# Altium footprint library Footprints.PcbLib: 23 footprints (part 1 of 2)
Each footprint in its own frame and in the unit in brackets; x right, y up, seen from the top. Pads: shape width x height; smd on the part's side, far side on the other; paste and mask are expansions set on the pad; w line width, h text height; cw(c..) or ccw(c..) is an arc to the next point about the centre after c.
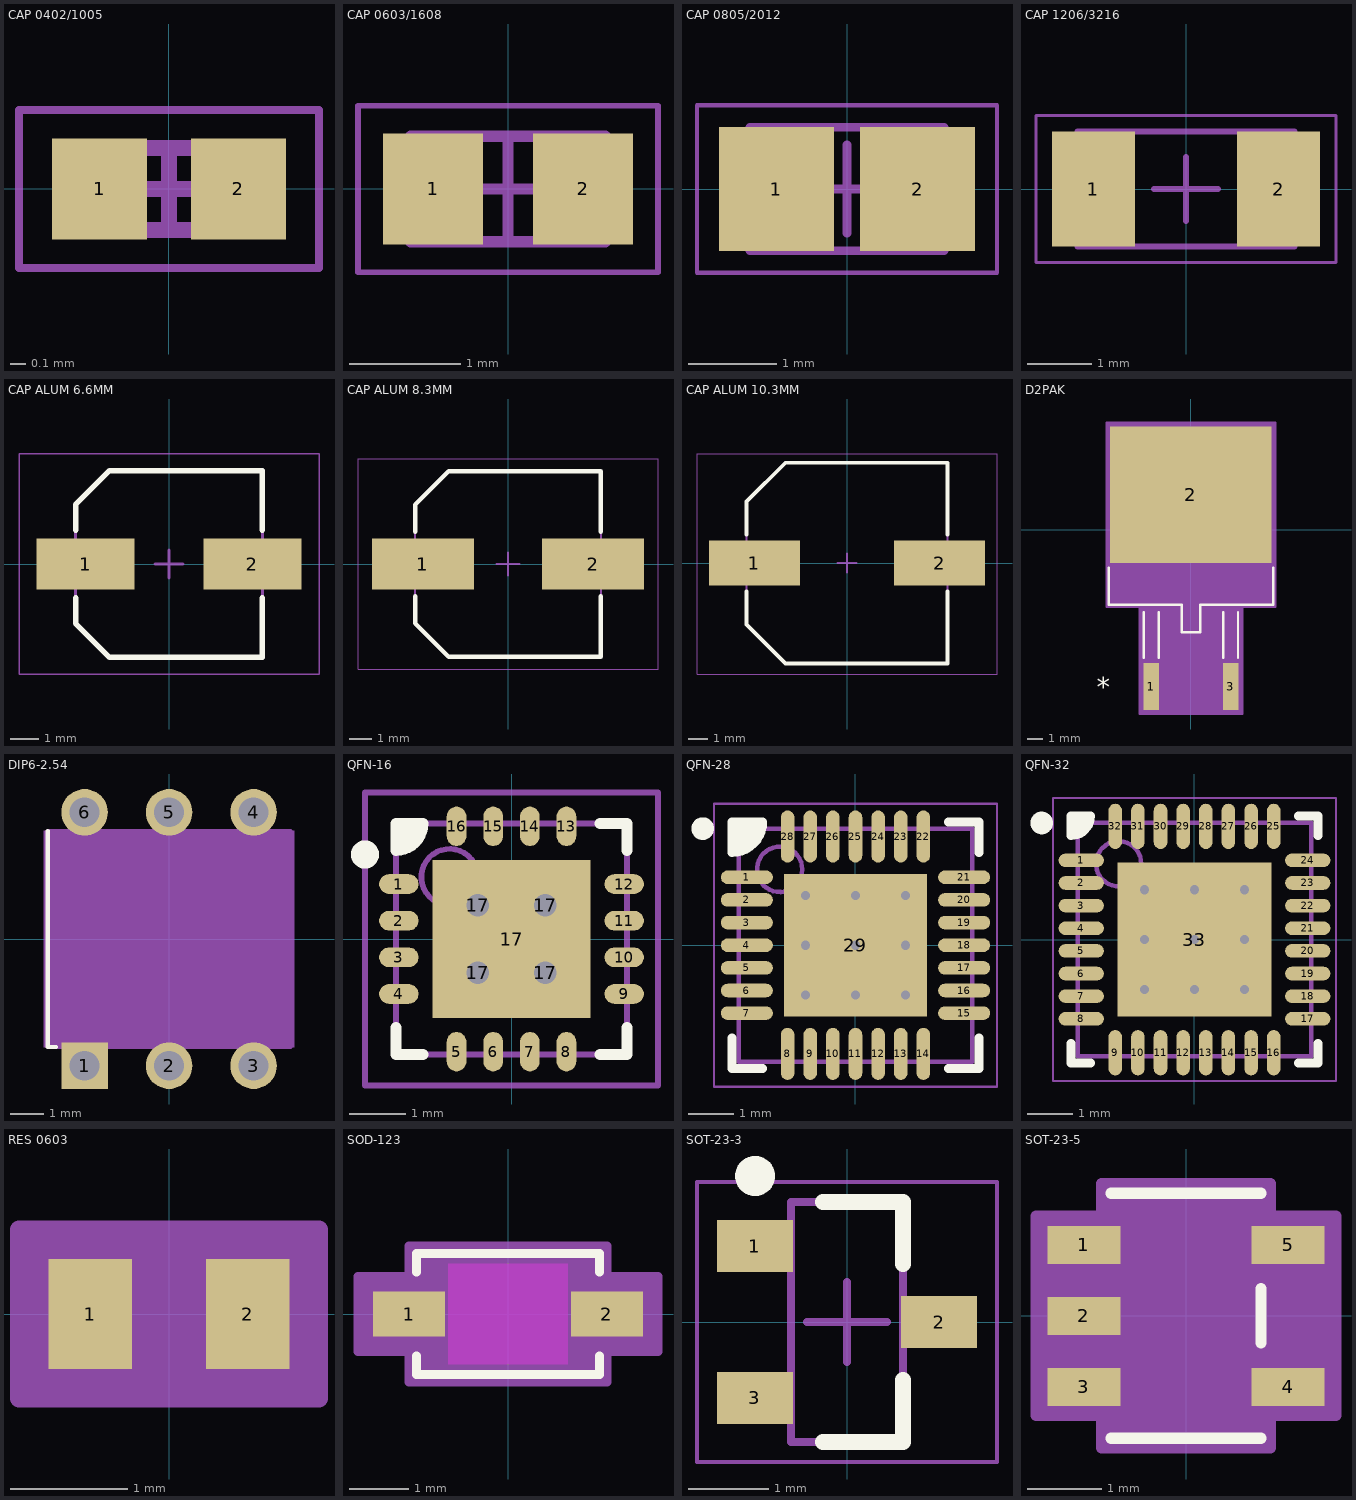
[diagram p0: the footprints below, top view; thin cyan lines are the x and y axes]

## CAP 0402/1005 [mm] "Chip Capacitor, 2-Leads, Body 1.02x0.51mm, IPC Medium Density"
height 0.52
pads (2):
  rect 0.6x0.64 smd: 1(-0.44,0) 2(0.44,0)
Mechanical 13:
  lines w0.1: -0.515,-0.26 0.515,-0.26 0.515,0.26 -0.515,0.26 -0.515,-0.26
Mechanical 15:
  lines w0.05: -0.95,-0.5 0.95,-0.5 0.95,0.5 -0.95,0.5 -0.95,-0.5
  lines w0.1: -0.26,0 0.26,0 ; 0,-0.26 0,0.26
3D body "0402 cap.STEP": height 0.52, standoff 0, extent -0.5,-0.262 0.5,0.262

## CAP 0603/1608 [mm] "Chip Capacitor, 2-Leads, Body 1.60x0.80mm, IPC Medium Density"
height 0.89
pads (2):
  rect 0.9x1 smd: 1(-0.675,0) 2(0.675,0)
Mechanical 13:
  lines w0.1: -0.875,-0.475 -0.875,0.475 0.875,0.475 0.875,-0.475 -0.875,-0.475
Mechanical 15:
  lines w0.05: -1.35,-0.75 -1.35,0.75 1.35,0.75 1.35,-0.75 -1.35,-0.75
  lines w0.1: -0.475,0 0.475,0 ; 0,-0.475 0,0.475
3D body "0603 cap.STEP": height 0.82, standoff 0, extent -0.8,-0.412 0.8,0.412

## CAP 0805/2012 [mm] "Chip Capacitor, 2-Leads, Body 2.00x1.20mm, IPC Medium Density"
height 1.15
pads (2):
  rect 1.3x1.4 smd: 1(-0.8,0) 2(0.8,0)
Mechanical 13:
  lines w0.1: -1.1,-0.7 1.1,-0.7 1.1,0.7 -1.1,0.7 -1.1,-0.7
Mechanical 15:
  lines w0.05: -1.7,-0.95 1.7,-0.95 1.7,0.95 -1.7,0.95 -1.7,-0.95
  lines w0.1: -0.5,0 0.5,0 ; 0,-0.5 0,0.5
3D body "0805 cap.STEP": height 1.26, standoff -0.02, extent -1,-0.637 1,0.637

## CAP 1206/3216 [mm] "Chip Capacitor, 2-Leads, Body 3.25x1.60mm, IPC Medium Density"
height 1.6
pads (2):
  rect 1.3x1.8 smd: 1(-1.45,0) 2(1.45,0)
Mechanical 13:
  lines w0.1: -1.7,-0.9 1.7,-0.9 1.7,0.9 -1.7,0.9 -1.7,-0.9
Mechanical 15:
  lines w0.05: -2.35,-1.15 2.35,-1.15 2.35,1.15 -2.35,1.15 -2.35,-1.15
  lines w0.1: -0.5,0 0.5,0 ; 0,-0.5 0,0.5
3D body "1206 cap.STEP": height 1.62, standoff 0, extent -1.6,-0.812 1.6,0.812

## CAP ALUM 6.6MM [mm] "Aluminum Electrolytic Capacitor, Body 6.60x6.60x7.70mm, IPC Low Density"
height 7.7
pads (2):
  rect 3.45x1.8 smd: 1(-2.95,0) 2(2.95,0)
Top Overlay:
  lines w0.2: -3.3,-1.2 -3.3,-2.1 -2.1,-3.3 3.3,-3.3 3.3,-1.2 ; -3.3,1.2 -3.3,2.1 -2.1,3.3 3.3,3.3 3.3,1.2
Mechanical 13:
  lines w0.1: -3.3,-2.1 -2.1,-3.3 3.3,-3.3 3.3,3.3 -2.1,3.3 -3.3,2.1 -3.3,-2.1
Mechanical 15:
  lines w0.05: -5.3,-3.9 -5.3,3.9 5.3,3.9 5.3,-3.9 -5.3,-3.9
  lines w0.1: -0.5,0 0.5,0 ; 0,-0.5 0,0.5
3D body "CAP ALUM 6_6mm.STEP": height 7.7, standoff 0, extent -3.5,-3.3 3.5,3.3

## CAP ALUM 8.3MM [mm] "Aluminum Electrolytic Capacitor, Body 8.30x8.30x10.50mm, IPC Low Density"
height 10.5
pads (2):
  rect 4.55x2.3 smd: 1(-3.8,0) 2(3.8,0)
Top Overlay:
  lines w0.2: -4.15,-1.45 -4.15,-2.65 -2.65,-4.15 4.15,-4.15 4.15,-1.45 ; -4.15,1.45 -4.15,2.65 -2.65,4.15 4.15,4.15 4.15,1.45
Mechanical 13:
  lines w0.1: -4.15,-2.65 -4.15,2.65 -2.65,4.15 4.15,4.15 4.15,-4.15 -2.65,-4.15 -4.15,-2.65
Mechanical 15:
  lines w0.05: -6.7,-4.7 6.7,-4.7 6.7,4.7 -6.7,4.7 -6.7,-4.7
  lines w0.1: -0.5,0 0.5,0 ; 0,-0.5 0,0.5
3D body "CAP ALUM 8_3mm.STEP": height 10.5, standoff 0, extent -4.95,-4.15 4.95,4.15

## CAP ALUM 10.3MM [mm] "Aluminum Electrolytic Capacitor, Body 10.30x10.30x10.50mm, IPC Low Density"
height 10.5
pads (2):
  rect 4.65x2.3 smd: 1(-4.75,0) 2(4.75,0)
Top Overlay:
  lines w0.2: -5.15,-1.45 -5.15,-3.15 -3.15,-5.15 5.15,-5.15 5.15,-1.45 ; -5.15,1.45 -5.15,3.15 -3.15,5.15 5.15,5.15 5.15,1.45
Mechanical 13:
  lines w0.1: -5.15,-3.15 -3.15,-5.15 5.15,-5.15 5.15,5.15 -3.15,5.15 -5.15,3.15 -5.15,-3.15
Mechanical 15:
  lines w0.05: -7.7,-5.7 -7.7,5.6 7.7,5.6 7.7,-5.7 -7.7,-5.7
  lines w0.1: -0.5,0 0.5,0 ; 0,-0.5 0,0.5
3D body "CAP ALUM 10_3mm.STEP": height 10.5, standoff 0, extent -5.8,-5.15 5.8,5.15

## D2PAK [mil]
pads (3):
  rect 39x118 smd paste+0 mask+0: 1(-100,-395) 3(100,-395)
  rect 407x343 smd paste+0 mask+0: 2(0,88.5)
Top Overlay:
  lines w6: -207.5,-95.47 -207.5,-189 -23.5,-189 -23.5,-258 23.5,-258 23.5,-189 207.5,-189 207.5,-95.47 ; -118.5,-322 -118.5,-208 ; -81.5,-322 -81.5,-208 ; 81.5,-322 81.5,-208 ; 118.5,-322 118.5,-208
  text "*" at -237.5,-420 h50
Mechanical 13:
  lines w1: -202.5,-184 202.5,-184 202.5,184 -202.5,184 -202.5,-184 ; -118.5,-440 -118.5,-184 -81.5,-184 -81.5,-440 -118.5,-440 ; -18.5,-253 -18.5,-184 18.5,-184 18.5,-253 -18.5,-253 ; 81.5,-440 81.5,-184 118.5,-184 118.5,-440 81.5,-440
  text "*" at -112.5,-199 h50
Mechanical 15:
  region: -212.5,-194 -212.5,194 -212.5,270 212.5,270 212.5,194 212.5,-194 129.5,-194 129.5,-464 -129.5,-464 -129.5,-194
  lines w6: -212.5,-194 -212.5,194 -212.5,270 212.5,270 212.5,194 212.5,-194 129.5,-194 129.5,-464 -129.5,-464 -129.5,-194 -212.5,-194
3D body "D2PAK_T2550_STM.step": height 181.1, standoff -2.01, extent -202.48,-440 202.48,239.02

## DIP6-2.54 [mm]
pads (6):
  rect 1.4x1.4 hole 0.9: 1(-2.54,-3.81)
  round 1.4 hole 0.9: 2(0,-3.81) 3(2.54,-3.81) 4(2.54,3.81) 5(0,3.81) 6(-2.54,3.81)
Top Overlay:
  lines w0.127: -3.65,3.25 -3.65,-3.25 -3.4,-3.25
Mechanical 13:
  lines w0.127: -3.65,-3.25 3.65,-3.25 ; -3.65,3.25 3.65,3.25
Mechanical 15:
  region: 3.76,-3.255 -3.766,-3.255 -3.766,3.25 3.76,3.25
3D body "4N35.STEP": height 3.81, standoff -3.94, extent -3.56,-4.405 3.56,4.405

## QFN-16 [mm] "QFN, 16-Leads, Body 4.1x4.1mm (max), Pitch 0.65mm, IPC Medium Density"
height 1
pads (21):
  oval 0.7x0.35 smd: 1(-2,0.975) 2(-2,0.325) 3(-2,-0.325) 4(-2,-0.975) 9(2,-0.975) 10(2,-0.325) 11(2,0.325) 12(2,0.975)
  oval 0.35x0.7 smd: 5(-0.975,-2) 6(-0.325,-2) 7(0.325,-2) 8(0.975,-2) 13(0.975,2) 14(0.325,2) 15(-0.325,2) 16(-0.975,2)
  round 0.8 hole 0.4 unplated: 17(-0.6,-0.6) 17(-0.6,0.6) 17(0.6,-0.6) 17(0.6,0.6)
  rect 2.8x2.8 smd: 17(0,0)
Top Overlay:
  circle w0.25: c-2.6,1.5 r0.125
  region: -2.05,2.05 -1.575,2.05 -1.575,1.925 -1.9,1.6 -2.05,1.6
  lines w0.2: -2.05,-1.575 -2.05,-2.05 -1.575,-2.05 ; 1.575,-2.05 2.05,-2.05 2.05,-1.575 ; 1.575,2.05 2.05,2.05 2.05,1.575 ; -2.05,1.575 ccw(c-2.05,2.05) -1.575,2.05 -2.05,2.05 -2.05,1.575
Mechanical 13:
  circle w0.1: c-1.1,1.1 r0.5
  lines w0.1: -2.05,-2.05 -2.05,2.05 2.05,2.05 2.05,-2.05 -2.05,-2.05
Mechanical 15:
  lines w0.1: -0.5,0 0.5,0 ; 0,-0.5 0,0.5 ; -2.6,-2.6 -2.6,2.6 2.6,2.6 2.6,-2.6 -2.6,-2.6
3D body: height 1, standoff 0.08, extent -2.05,-2.05 2.05,2.05

## QFN-28 [mm] "QFN, 28-Leads, Body 5.00x5.00mm, Pitch 0.50mm, Thermal Pad 3.15x3.15mm, IPC Medium Density"
height 1
pads (29):
  oval 1.15x0.3 smd: 1(-2.4,1.5) 2(-2.4,1) 3(-2.4,0.5) 4(-2.4,0) 5(-2.4,-0.5) 6(-2.4,-1) 7(-2.4,-1.5) 15(2.4,-1.5) 16(2.4,-1) 17(2.4,-0.5) 18(2.4,0) 19(2.4,0.5) 20(2.4,1) 21(2.4,1.5)
  oval 0.3x1.15 smd: 8(-1.5,-2.4) 9(-1,-2.4) 10(-0.5,-2.4) 11(0,-2.4) 12(0.5,-2.4) 13(1,-2.4) 14(1.5,-2.4) 22(1.5,2.4) 23(1,2.4) 24(0.5,2.4) 25(0,2.4) 26(-0.5,2.4) 27(-1,2.4) 28(-1.5,2.4)
  rect 3.15x3.15 smd: 29(0,0)
via 1.1,-1.1 diameter 0.5 hole 0.2
via 0,-1.1 diameter 0.5 hole 0.2
via -1.1,-1.1 diameter 0.5 hole 0.2
via 1.1,0 diameter 0.5 hole 0.2
via 0,0 diameter 0.5 hole 0.2
via -1.1,0 diameter 0.5 hole 0.2
via 1.1,1.1 diameter 0.5 hole 0.2
via 0,1.1 diameter 0.5 hole 0.2
via -1.1,1.1 diameter 0.5 hole 0.2
Top Overlay:
  circle w0.25: c-3.375,2.575 r0.125
  region: -2.725,2.725 -2.05,2.725 -2.05,2.659 -2.076,2.528 -2.127,2.405 -2.201,2.295 -2.295,2.201 -2.405,2.127 -2.528,2.076 -2.659,2.05 -2.725,2.05
  lines w0.2: -2.725,-2.05 -2.725,-2.725 -2.05,-2.725 ; 2.05,-2.725 2.725,-2.725 2.725,-2.05 ; 2.05,2.725 2.725,2.725 2.725,2.05 ; -2.725,2.05 ccw(c-2.725,2.725) -2.05,2.725 -2.725,2.725 -2.725,2.05
Mechanical 13:
  circle w0.1: c-1.675,1.675 r0.5
  lines w0.1: -2.575,-2.575 2.575,-2.575 2.575,2.575 -2.575,2.575 -2.575,-2.575
Mechanical 15:
  lines w0.05: -3.125,-3.125 3.125,-3.125 3.125,3.125 -3.125,3.125 -3.125,-3.125
  lines w0.1: -0.5,0 0.5,0 ; 0,-0.5 0,0.5
3D body: height 1, standoff 0.01, extent -2.575,-2.575 2.575,2.575

## QFN-32 [mm] "QFN, 32-Leads, Body 5.00x5.00mm, Pitch 0.50mm, Thermal Pad 3.40x3.40mm, IPC Medium Density"
height 1
pads (33):
  oval 1x0.3 smd: 1(-2.5,1.75) 2(-2.5,1.25) 3(-2.5,0.75) 4(-2.5,0.25) 5(-2.5,-0.25) 6(-2.5,-0.75) 7(-2.5,-1.25) 8(-2.5,-1.75) 17(2.5,-1.75) 18(2.5,-1.25) 19(2.5,-0.75) 20(2.5,-0.25) 21(2.5,0.25) 22(2.5,0.75) 23(2.5,1.25) 24(2.5,1.75)
  oval 0.3x1 smd: 9(-1.75,-2.5) 10(-1.25,-2.5) 11(-0.75,-2.5) 12(-0.25,-2.5) 13(0.25,-2.5) 14(0.75,-2.5) 15(1.25,-2.5) 16(1.75,-2.5) 25(1.75,2.5) 26(1.25,2.5) 27(0.75,2.5) 28(0.25,2.5) 29(-0.25,2.5) 30(-0.75,2.5) 31(-1.25,2.5) 32(-1.75,2.5)
  rect 3.4x3.4 smd: 33(0,0)
via 1.1,-1.1 diameter 0.5 hole 0.2
via 0,-1.1 diameter 0.5 hole 0.2
via -1.1,-1.1 diameter 0.5 hole 0.2
via 1.1,0 diameter 0.5 hole 0.2
via 0,0 diameter 0.5 hole 0.2
via -1.1,0 diameter 0.5 hole 0.2
via 1.1,1.1 diameter 0.5 hole 0.2
via 0,1.1 diameter 0.5 hole 0.2
via -1.1,1.1 diameter 0.5 hole 0.2
Top Overlay:
  circle w0.25: c-3.375,2.575 r0.125
  region: -2.725,2.725 -2.3,2.725 -2.3,2.64 -2.365,2.484 -2.484,2.365 -2.64,2.3 -2.725,2.3
  lines w0.2: -2.725,-2.3 -2.725,-2.725 -2.3,-2.725 ; 2.3,-2.725 2.725,-2.725 2.725,-2.3 ; 2.3,2.725 2.725,2.725 2.725,2.3 ; -2.725,2.3 ccw(c-2.725,2.725) -2.3,2.725 -2.725,2.725 -2.725,2.3
Mechanical 13:
  circle w0.1: c-1.675,1.675 r0.5
  lines w0.1: -2.575,-2.575 2.575,-2.575 2.575,2.575 -2.575,2.575 -2.575,-2.575
Mechanical 15:
  lines w0.05: -3.125,-3.125 3.125,-3.125 3.125,3.125 -3.125,3.125 -3.125,-3.125
  lines w0.1: -0.5,0 0.5,0 ; 0,-0.5 0,0.5
3D body: height 1, standoff 0.01, extent -2.575,-2.575 2.575,2.575

## RES 0603 [mil]
pads (2):
  rect 28x37 smd paste-18.5 mask-18.5: 1(-26.5,0) 2(26.5,0)
Mechanical 13:
  lines w1: -32.5,-18.5 -32.5,18.5 ; -32.5,-18.5 -12.5,-18.5 -12.5,18.5 -32.5,18.5 ; -32.5,-18.5 32.5,-18.5 ; -32.5,-18.5 -32.5,18.5 ; -32.5,18.5 32.5,18.5 ; 32.5,-18.5 12.5,-18.5 12.5,18.5 32.5,18.5 ; 32.5,-18.5 32.5,18.5 ; 32.5,-18.5 32.5,18.5
Mechanical 15:
  region: 50.5,-28.5 -50.5,-28.5 -50.5,28.5 50.5,28.5
  lines w6: -50.5,-28.5 -50.5,28.5 50.5,28.5 50.5,-28.5 -50.5,-28.5
3D body "RES_CRCW_0603.step": height 20, standoff 0, extent -32.52,-18.5 32.52,18.5

## SOD-123 [mil]
pads (2):
  rect 48x30 smd paste+0 mask+0: 1(-66,0) 2(66,0)
Top Overlay:
  lines w6: -61,-28.1 -61,-40.5 61,-40.5 61,-28.1 ; -61,28.1 -61,40.5 61,40.5 61,28.1
Keep-Out Layer:
  region: -40,-33.5 -40,33.5 40,33.5 40,-33.5
Mechanical 13:
  lines w1: -56,-17.75 -38.25,-35.5 ; -56,17.75 -38.25,35.5 ; -76,-14 -76,14 -56,14 -56,-14 -76,-14 ; -56,-35.5 56,-35.5 56,35.5 -56,35.5 -56,-35.5 ; 56,-14 56,14 76,14 76,-14 56,-14
  text "*" at -58.5,-25 h50
Mechanical 15:
  region: -66,-25 -100,-25 -100,25 -66,25 -66,45.5 66,45.5 66,25 100,25 100,-25 66,-25 66,-45.5 -66,-45.5
  lines w6: -100,-25 -100,25 -66,25 -66,45.5 66,45.5 66,25 100,25 100,-25 66,-25 66,-45.5 -66,-45.5 -66,-25 -100,-25
3D body "SOD-123_ONS.step": height 53.11, standoff 0, extent -75.98,-35.51 75.98,35.51

## SOT-23-3 [mm] "SOT23, 3-Leads, Body 2.90x2.40mm, Pitch 0.95mm, IPC Medium Density"
height 1.35
pads (3):
  rect 0.95x0.65 smd: 1(-1.15,0.95) 2(1.15,0) 3(-1.15,-0.95)
Top Overlay:
  circle w0.25: c-1.15,1.825 r0.125
  lines w0.2: -0.3,-1.5 0.7,-1.5 0.7,-0.725 ; -0.3,1.5 0.7,1.5 0.7,0.725
Mechanical 13:
  lines w0.1: -0.7,-1.5 -0.7,1.5 0.7,1.5 0.7,-1.5 -0.7,-1.5
Mechanical 15:
  lines w0.05: -1.875,-1.75 -1.875,1.75 1.875,1.75 1.875,-1.75 -1.875,-1.75
  lines w0.1: -0.5,0 0.5,0 ; 0,-0.5 0,0.5
3D body "sot-23-3.STEP": height 1.5, standoff 0, extent -1.41,-1.45 1.411,1.45

## SOT-23-5 [mil]
pads (5):
  rect 38.5x20 smd paste+0 mask+0: 1(-53.75,37.4) 2(-53.75,0) 3(-53.75,-37.4) 4(53.75,-37.4) 5(53.75,37.4)
Top Overlay:
  lines w6: -39.5,-64.5 39.5,-64.5 ; -39.5,64.5 39.5,64.5 ; 39.5,-14.3 39.5,14.3
Mechanical 13:
  lines w0: -12,59.5 ccw(c0,59.5) 12,59.5
  lines w1: -59,-47.4 -59,-27.4 -34.5,-27.4 -34.5,-47.4 -59,-47.4 ; -59,-10 -59,10 -34.5,10 -34.5,-10 -59,-10 ; -59,27.4 -59,47.4 -34.5,47.4 -34.5,27.4 -59,27.4 ; -34.5,-59.5 34.5,-59.5 34.5,59.5 -34.5,59.5 -34.5,-59.5 ; 34.5,-47.4 34.5,-27.4 59,-27.4 59,-47.4 34.5,-47.4 ; 34.5,27.4 34.5,47.4 59,47.4 59,27.4 34.5,27.4
  text "*" at -37,9.4 h50
Mechanical 15:
  region: 44.5,-69.5 -44.5,-69.5 -44.5,-52.4 -79,-52.4 -79,52.4 -44.5,52.4 -44.5,69.5 44.5,69.5 44.5,52.4 79,52.4 79,-52.4 44.5,-52.4
  lines w6: -79,-52.4 -44.5,-52.4 -44.5,-69.5 44.5,-69.5 44.5,-52.4 79,-52.4 79,52.4 44.5,52.4 44.5,69.5 -44.5,69.5 -44.5,52.4 -79,52.4 -79,-52.4
3D body "SOT-23-5_M5_MCH.step": height 51.1, standoff 0, extent -59.02,-59.49 59.02,59.49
